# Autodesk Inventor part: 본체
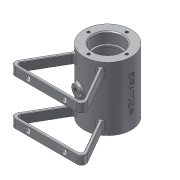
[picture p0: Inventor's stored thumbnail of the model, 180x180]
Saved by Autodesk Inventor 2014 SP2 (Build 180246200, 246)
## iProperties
Created: 2016-03
Part Number: 본체
Material: 알루미늄 6061
Document SubType Name: Modeling
Designer: 손기택
Density: 2.71 g/cm^3
Appearance: 알루미늄 - 평지
Mass: 214.196 g
Surface Area: 336.703 cm^2
Volume: 79.0391 cm^3
Author: 손기택
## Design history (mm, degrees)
sketch "스케치1"
  geometry: C1 r 26 at (0, 0); 1 further point
  constraints: 1 centre point, 1 coincident
  dimensions: "d0" = 52 diameter of C1
extrude "돌출1" new body sketch "스케치1" stored distance "d1" = 70; taper "d2" = 0 deg
sketch "스케치2"
  geometry: L1 (13, -22.517)-(37.528, -65); L2 (0, 0)-(100, 0); L3 (0, 0)-(105.078, 0); L4 (0, -65)-(37.528, -65); L5 (42.724, -68)-(13.224, -16.905); L6 (0, -68)-(42.724, -68); L7 (0, -16)-(0, -80); L8 (-13, -22.517)-(-37.528, -65); L9 (0, -68)-(-42.724, -68); L10 (0, -65)-(-37.528, -65); L11 (-42.724, -68)-(-13.224, -16.905); C1 r 26 at (0, 0) reference; A1 r 26 centre (0, 0) between (-13, -22.517) and (13, -22.517); A2 r 26 centre (0, 0) between (-15.511, -20.866) and (15.511, -20.866); 6 further points
  constraints: 22 end point, 8 point on circle, 4 point on line, 4 symmetric about line, 2 centre point, 2 coincident, 2 horizontal, 1 perpendicular
  dimensions: "d4" = 60 deg angle of L1 L2; "d73" = 65 distance from line of L4 point (0, 0); "d107" = 3 distance between parallel lines of L5 L1; "d108" = 3 distance between parallel lines of L6 L4
sketch "스케치4"
  geometry: C1 r 16 at (0, 0); 1 further point
  constraints: 1 centre point, 1 coincident
  dimensions: "d11" = 32 diameter of C1
extrude "돌출4" cut sketch "스케치4" distance "d12" = 12; taper "d13" = 0 deg
sketch "스케치5"
  geometry: C1 r 14 at (0, 0); 1 further point
  constraints: 1 centre point, 1 coincident
  dimensions: "d14" = 28 diameter of C1
extrude "돌출5" cut sketch "스케치5" distance "d15" = 2; taper "d16" = 0 deg
sketch "스케치6"
  geometry: C1 r 21 at (0, 0); 1 further point
  constraints: 1 centre point, 1 coincident
  dimensions: "d17" = 42 diameter of C1
extrude "돌출6" cut sketch "스케치6" distance "d18" = 42; taper "d19" = 0 deg
chamfer "모따기1" distance "d20" = 1; stored, may be unused: second distance "d21" = 2, angle "d22" = 45 deg
fillet "모깎기1" dims "d23" = 3
sketch "스케치7"
  geometry: C1 r 26 at (0, 0) reference; 2 further points
  dimensions: "d24" = 21 distance of point (0, 0) point (0, 21)
hole "구멍1" sketch "스케치7" at (0, 21) diameter "d25" = 3.242; stored, may be unused: countersink angle "d29" = 90 deg, drill point angle "d31" = 118 deg; dims "d26" = 8, "d27" = 4, "d28" = 2, "d30" = 10
node "작업 평면1"
sketch "스케치8"
  geometry: L1 (3.002, 29.901)-(3.002, -29.901); L2 (3.002, -29.901)-(-3.002, -29.901); L3 (-3.002, -29.901)-(-3.002, 29.901); L4 (-3.002, 29.901)-(3.002, 29.901); L5 (-26, -35)-(26, -35) reference; L6 (26, 35)-(-26, 35) reference; 3 further points
  constraints: 2 midpoint, 1 horizontal alignment, 1 vertical alignment, 2 other
feature "엠보싱1" sketch "스케치8" dims "d36" = 0.5, "d37" = 0
node "작업 평면2"
sketch "스케치9"
  geometry: C1 r 5 at (0, 0); 1 further point
  constraints: 1 centre point, 1 coincident
  dimensions: "d39" = 10 diameter of C1
extrude "돌출7" join sketch "스케치9" stored distance "d40" = 42; taper "d41" = 0 deg
sketch "스케치10"
  geometry: 2 further points
  constraints: 1 coincident
hole "구멍2" sketch "스케치10" at (0, 0) diameter "d42" = 5.188; stored, may be unused: countersink angle "d46" = 90 deg, drill point angle "d48" = 0 deg; dims "d43" = 9, "d44" = 4, "d45" = 2, "d47" = 9
sketch "스케치11"
  geometry: L1 (0, 0)-(29, 0); 1 further point
  constraints: 2 end point, 1 horizontal
node "작업 평면3"
node "작업 평면4"
fillet "모깎기4" dims "d85" = 2
fillet "모깎기5" dims "d86" = 0.3
sketch "스케치17"
  geometry: L1 (0, 0)-(26, 0); 1 further point
  constraints: 2 end point, 1 horizontal
node "작업 평면5"
node "작업 평면6"
sketch "스케치18"
  geometry: C1 r 6 at (0, 0); 1 further point
  constraints: 1 centre point, 1 coincident
  dimensions: "d97" = 12 diameter of C1
extrude "돌출13" join sketch "스케치18" stored distance "d98" = 40; taper "d99" = 0 deg
sketch "스케치19"
  geometry: 2 further points
  constraints: 1 coincident
hole "구멍4" sketch "스케치19" at (0, 0) diameter "d100" = 5.188; stored, may be unused: countersink angle "d104" = 90 deg, drill point angle "d106" = 0 deg; dims "d101" = 9, "d102" = 4, "d103" = 2, "d105" = 9
extrude "돌출14" join sketch "스케치2" stored distance "d110" = 60; taper "d111" = 0 deg
sketch "스케치21"
  geometry: L1 (-37.528, -65)-(-13, -22.517) reference; L2 (-15.511, -20.866)-(-42.724, -68) reference; L3 (-42.724, -68)-(42.724, -68) reference; L4 (42.724, -68)-(15.511, -20.866) reference; L5 (13, -22.517)-(37.528, -65) reference; L6 (37.528, -65)-(-37.528, -65) reference; A1 r 26 centre (0, 0) between (-15.511, -20.866) and (-13, -22.517) reference; A2 r 26 centre (0, 0) between (13, -22.517) and (15.511, -20.866) reference; 1 further point
extrude "돌출15" cut sketch "스케치21" stored distance "d112" = 40; taper "d113" = 0 deg
fillet "모깎기13" dims "d114" = 5
fillet "모깎기14" dims "d115" = 2
fillet "모깎기15" dims "d116" = 3
fillet "모깎기16" dims "d117" = 3
fillet "모깎기17" dims "d118" = 3
fillet "모깎기18" dims "d119" = 0.5
fillet "모깎기19" dims "d120" = 0.5
sketch "스케치22"
  geometry: L1 (0, 0)-(64.663, 0) reference; L2 (0, -9)-(0, 0) reference; L3 (64.663, -9)-(0, -9) reference; L4 (64.663, 0)-(64.663, -9) reference; L5 (30.711, -4.5)-(33.953, -4.5) reference; L6 (30.711, -4.5)-(33.953, -4.5) reference; L7 (9.711, -4.5)-(12.953, -4.5) reference; C1 r 3 at (12.332, -4.5); C2 r 3 at (52.332, -4.5); 1 further point
  constraints: 2 centre point
  dimensions: "d123" = 6 diameter of C1; "d124" = 6 diameter of C2
extrude "돌출16" cut sketch "스케치22" stored distance "d125" = 10; taper "d126" = 0 deg
node "솔리드1"
mirror "대칭1"
pattern_circular "원형 패턴1" dims angle "d33" = 360 deg
mirror "대칭2"
mirror "대칭5"
node "투영된 루프2"
node "투영된 루프6"
node "투영된 루프7"
other parameters: "d35" = 26, "d38" = 29, "d51" = 3, "d96" = 3
